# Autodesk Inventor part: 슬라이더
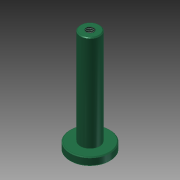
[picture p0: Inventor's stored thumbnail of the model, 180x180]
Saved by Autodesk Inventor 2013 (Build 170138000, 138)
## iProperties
Created: 2016-02
Part Number: 슬라이더
Material: 일반
Document SubType Name: Modeling
Designer: mduedu
Density: 8.08 g/cm^3
Mass: 72.5507 g
Surface Area: 37.669 cm^2
Volume: 8.97904 cm^3
Author: mduedu
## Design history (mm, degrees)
sketch "스케치1"
  geometry: C1 r 12.5 at (0, 0); 1 further point
  constraints: 1 centre point, 1 coincident
  dimensions: "d0" = 25 diameter of C1
extrude "돌출1" new body sketch "스케치1" distance "d1" = 5; taper "d2" = 0 deg
sketch "스케치2"
  geometry: C1 r 6 at (0, 0); 1 further point
  constraints: 1 centre point, 1 coincident
  dimensions: "d3" = 12 diameter of C1
extrude "돌출2" join sketch "스케치2" distance "d4" = 60; taper "d5" = 0 deg
chamfer "모따기1" distance "d6" = 0.5; stored, may be unused: second distance "d7" = 2, angle "d8" = 45 deg
hole "구멍1" diameter "d11" = 4.917; stored, may be unused: countersink angle "d15" = 90 deg, drill point angle "d17" = 118 deg; dims "d9" = 10, "d10" = 10, "d12" = 10, "d13" = 4, "d14" = 2, "d16" = 12
chamfer "모따기2" distance "d18" = 0.5; stored, may be unused: second distance "d19" = 2, angle "d20" = 45 deg
sketch "스케치3"
  geometry: L1 (-12.5, 4.5)-(-12, 5) reference; L2 (-12, 5)-(-6, 5) reference; L3 (-6, 5)-(-6, 64.5) reference; L4 (-6, 64.5)-(-5.5, 65) reference; L5 (-5.5, 65)-(-2.458, 65) reference; L6 (-2.458, 65)-(-2.458, 53) reference; L7 (-2.458, 53)-(0, 51.523) reference; L8 (0, 51.523)-(2.458, 53) reference; L9 (2.458, 53)-(2.458, 65) reference; L10 (2.458, 65)-(5.5, 65) reference; L11 (5.5, 65)-(6, 64.5) reference; L12 (6, 64.5)-(6, 5) reference; L13 (6, 5)-(12, 5) reference; L14 (12, 5)-(12.5, 4.5) reference; L15 (12.5, 4.5)-(12.5, 0.5) reference; L16 (12.5, 0.5)-(12, 0) reference; L17 (12, 0)-(-12, 0) reference; L18 (-12, 0)-(-12.5, 0.5) reference; L19 (-12.5, 0.5)-(-12.5, 4.5) reference; 1 further point
  node "절단 모서리 투영1"
node "솔리드1"
